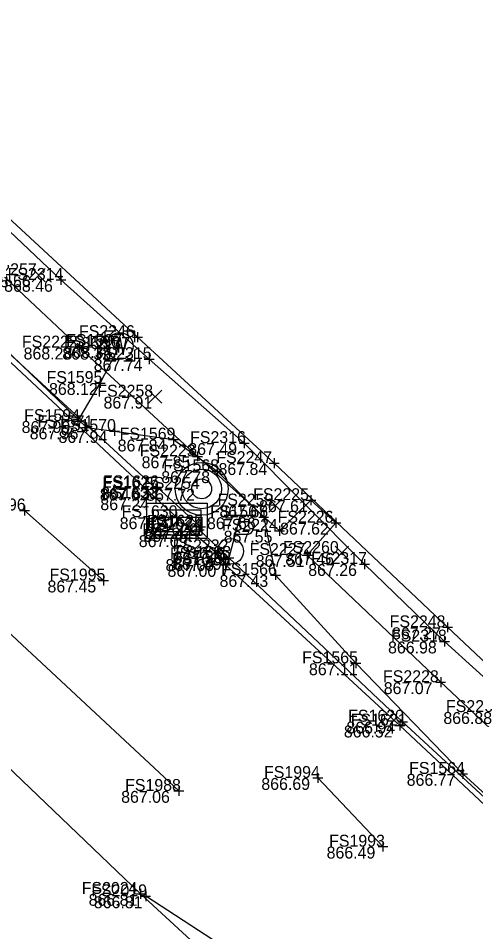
# Model space of a CAD drawing. Extents: x 1479420 to 1479833, y 379731 to 380103.
# Drawn here: x 1479719.9 to 1479766, y 379820.1 to 379912.2 of the extents above; entities that cross this region are included whole.
import ezdxf

# ---------------------------------------------------------------- set-up
doc = ezdxf.new("R2010")
doc.units = 0
for name, color, linetype in [('DR_X_Cells', 7, 'Continuous'), ('GK_Drainage_Nodes', 7, 'Continuous'), ('PM_X_Channelizing_Line', 7, 'Continuous'), ('PM_X_CL_Double_Solid', 7, 'Continuous'), ('PM_X_Lane_Line', 7, 'Continuous'), ('PV_X_Curb', 7, 'Continuous'), ('PV_X_Walk', 7, 'Continuous'), ('SV_X_Random_Point', 7, 'Continuous'), ('SV_X_Shot_Marker', 7, 'Continuous'), ('SV_X_Text_Elevation', 7, 'Continuous'), ('SV_X_Text_Name', 7, 'Continuous'), ('UT_X_Gas', 7, 'Continuous'), ('UT_X_Misc_Cells', 7, 'Continuous'), ('UT_X_Water', 7, 'Continuous'), ('UT_X_Water_Cells', 7, 'Continuous')]:
    doc.layers.add(name, color=color, linetype=linetype)

msp = doc.modelspace()

# ---------------------------------------------------------------- linework, layer by layer
at = {"layer": 'DR_X_Cells'}
for p, q in [((1479733.43, 379860.105), (1479735.184, 379861.863)), ((1479733.43, 379861.237), (1479734.054, 379861.863)), ((1479734.486, 379860.03), (1479736.314, 379861.863)), ((1479735.615, 379860.03), (1479737.444, 379861.863)), ((1479736.745, 379860.03), (1479738.43, 379861.719)), ((1479737.875, 379860.03), (1479738.43, 379860.587))]:
    msp.add_line(p, q, dxfattribs=at)
for points in [[(1479732.888, 379863.281), (1479738.972, 379863.281), (1479738.972, 379859.697), (1479732.888, 379859.697)], [(1479733.555, 379862.613), (1479738.305, 379862.613), (1479738.305, 379860.363), (1479733.555, 379860.363)], [(1479733.43, 379861.863), (1479738.43, 379861.863), (1479738.43, 379860.03), (1479733.43, 379860.03)]]:
    msp.add_lwpolyline(points, close=True, dxfattribs=at)
for radius in [2.667, 2, 1]:
    msp.add_circle((1479738.405, 379864.71), radius, dxfattribs=at)
at = {"layer": 'GK_Drainage_Nodes'}
for p, q in [((1479738.405, 379866.71), (1479738.405, 379866.71)), ((1479738.405, 379864.71), (1479738.405, 379864.71)), ((1479738.405, 379864.71), (1479738.405, 379864.71)), ((1479738.405, 379864.71), (1479738.405, 379864.71)), ((1479735.93, 379863.28), (1479735.93, 379863.28)), ((1479735.93, 379862.613), (1479735.93, 379862.613)), ((1479738.405, 379862.71), (1479738.405, 379862.71)), ((1479735.93, 379861.863), (1479735.93, 379861.863)), ((1479735.93, 379861.863), (1479735.93, 379861.863)), ((1479733.555, 379861.488), (1479733.555, 379861.488)), ((1479735.93, 379861.488), (1479735.93, 379861.488)), ((1479738.305, 379861.488), (1479738.305, 379861.488)), ((1479735.93, 379860.363), (1479735.93, 379860.363)), ((1479735.93, 379859.697), (1479735.93, 379859.697))]:
    msp.add_line(p, q, dxfattribs=at)
msp.add_circle((1479738.405, 379864.71), 2, dxfattribs=at)
at = {"layer": 'PM_X_Channelizing_Line'}
msp.add_lwpolyline([(1479685.324, 379881.456), (1479709.405, 379859.144), (1479736.1, 379834.256)], dxfattribs=at)
at = {"layer": 'PM_X_CL_Double_Solid'}
for points in [[(1479794.219, 379768.772), (1479779.093, 379781.771), (1479763.159, 379795.427), (1479746.619, 379810.624), (1479732.239, 379823.873), (1479714.719, 379840.653), (1479700.713, 379853.615), (1479677.934, 379875.066)], [(1479803.529, 379770.896), (1479781.948, 379790.708), (1479777.891, 379794.074), (1479768.812, 379800.571), (1479752.353, 379810.888), (1479732.762, 379823.628)]]:
    msp.add_lwpolyline(points, dxfattribs=at)
at = {"layer": 'PM_X_Lane_Line'}
for p, q in [((1479728.499, 379855.469), (1479720.54, 379862.536)), ((1479756.669, 379828.635), (1479750.1, 379835.56))]:
    msp.add_line(p, q, dxfattribs=at)
at = {"layer": 'PV_X_Curb'}
for points in [[(1479714.573, 379931.716), (1479714.771, 379922.599), (1479714.229, 379900.013), (1479714.491, 379898.192), (1479715.218, 379896.002), (1479717.036, 379893.796), (1479731.944, 379880.013), (1479745.709, 379867.308), (1479763.187, 379850.751), (1479775.061, 379839.578), (1479781.928, 379833.121), (1479783.777, 379830.713), (1479784.214, 379828.705), (1479783.141, 379825.906)], [(1479818.811, 379784.125), (1479817.439, 379785.583), (1479804.233, 379798.167), (1479791.741, 379810.033), (1479778.638, 379821.983), (1479775.464, 379824.819), (1479758.378, 379840.845), (1479740.8, 379857.042), (1479740.592, 379857.626), (1479737.808, 379860.038), (1479735.87, 379861.852), (1479733.787, 379863.763), (1479718.701, 379877.898), (1479705.478, 379890.334), (1479700.95, 379894.575), (1479699.048, 379897.264), (1479697.778, 379899.5), (1479696.445, 379902.732), (1479695.776, 379905.397), (1479695.475, 379907.419), (1479695.142, 379911.53), (1479695.083, 379915.321)], [(1479783.191, 379825.805), (1479782.298, 379824.723), (1479781.461, 379824.102), (1479780.469, 379823.552), (1479779.204, 379823.559), (1479778.041, 379823.771), (1479776.54, 379824.685), (1479775.613, 379825.569), (1479758.651, 379841.237), (1479741.143, 379857.755), (1479738.162, 379860.576), (1479738.292, 379860.892), (1479733.926, 379864.875), (1479733.77, 379864.743), (1479718.903, 379878.446), (1479705.833, 379890.72), (1479701.383, 379894.844), (1479699.526, 379897.551), (1479698.177, 379899.762), (1479696.913, 379902.812), (1479696.188, 379905.546), (1479696.149, 379907.481), (1479695.686, 379911.644), (1479695.62, 379915.117)]]:
    msp.add_lwpolyline(points, dxfattribs=at)
at = {"layer": 'PV_X_Walk'}
msp.add_lwpolyline([(1479714.407, 379931.65), (1479709.589, 379929.394), (1479706.362, 379927.006), (1479703.827, 379924.359), (1479702.38, 379922.179), (1479701.604, 379920.676), (1479701.232, 379918.285), (1479701.216, 379916.698), (1479701.871, 379912.679), (1479703.861, 379906.887), (1479705.425, 379903.147), (1479707.313, 379899.269), (1479709.707, 379895.256), (1479713.76, 379890.533), (1479726.083, 379878.959), (1479737.973, 379867.989), (1479746.242, 379860.487), (1479749.391, 379863.573), (1479751.936, 379861.299), (1479749.037, 379858.043), (1479762.483, 379845.218), (1479775.26, 379833.23), (1479781.252, 379827.717), (1479783.036, 379825.875)], dxfattribs=at)
at = {"layer": 'SV_X_Random_Point'}
for p, q in [((1479721.315, 379885.587), (1479722.649, 379886.922)), ((1479721.315, 379886.922), (1479722.649, 379885.587)), ((1479733.054, 379873.34), (1479734.388, 379874.675)), ((1479733.054, 379874.675), (1479734.388, 379873.34)), ((1479745.164, 379862.362), (1479746.498, 379863.697)), ((1479745.164, 379863.697), (1479746.498, 379862.362)), ((1479751.868, 379857.584), (1479753.202, 379858.919)), ((1479751.868, 379858.919), (1479753.202, 379857.584))]:
    msp.add_line(p, q, dxfattribs=at)
at = {"layer": 'SV_X_Shot_Marker'}
for p, q in [((1479723.725, 379885.781), (1479724.725, 379885.781)), ((1479724.225, 379886.281), (1479724.225, 379885.281)), ((1479724.225, 379885.781), (1479724.225, 379885.781)), ((1479731.444, 379880.013), (1479732.444, 379880.013)), ((1479731.944, 379880.513), (1479731.944, 379879.513)), ((1479731.944, 379880.013), (1479731.944, 379880.013)), ((1479726.083, 379879.459), (1479726.083, 379878.459)), ((1479730.011, 379879.447), (1479730.011, 379878.447)), ((1479725.583, 379878.959), (1479726.583, 379878.959)), ((1479726.083, 379878.959), (1479726.083, 379878.959)), ((1479729.511, 379878.947), (1479730.511, 379878.947)), ((1479730.011, 379878.947), (1479730.011, 379878.947)), ((1479733.117, 379878.295), (1479733.117, 379877.295)), ((1479732.617, 379877.795), (1479733.617, 379877.795)), ((1479733.117, 379877.795), (1479733.117, 379877.795)), ((1479728.18, 379875.882), (1479728.18, 379874.882)), ((1479727.68, 379875.382), (1479728.68, 379875.382)), ((1479728.18, 379875.382), (1479728.18, 379875.382)), ((1479725.91, 379872.046), (1479725.91, 379871.046)), ((1479725.41, 379871.546), (1479726.41, 379871.546)), ((1479725.91, 379871.546), (1479725.91, 379871.546)), ((1479726.29, 379870.913), (1479727.29, 379870.913)), ((1479726.79, 379871.413), (1479726.79, 379870.413)), ((1479726.79, 379870.913), (1479726.79, 379870.913)), ((1479729.608, 379871.044), (1479729.608, 379870.044)), ((1479729.108, 379870.544), (1479730.108, 379870.544)), ((1479729.608, 379870.544), (1479729.608, 379870.544)), ((1479735.551, 379870.184), (1479735.551, 379869.184)), ((1479735.051, 379869.684), (1479736.051, 379869.684)), ((1479735.551, 379869.684), (1479735.551, 379869.684)), ((1479742.197, 379869.326), (1479743.197, 379869.326)), ((1479742.697, 379869.826), (1479742.697, 379868.826)), ((1479742.697, 379869.326), (1479742.697, 379869.326)), ((1479737.973, 379868.489), (1479737.973, 379867.489)), ((1479737.473, 379867.989), (1479738.473, 379867.989)), ((1479737.973, 379867.989), (1479737.973, 379867.989)), ((1479745.209, 379867.308), (1479746.209, 379867.308)), ((1479745.709, 379867.808), (1479745.709, 379866.808)), ((1479745.709, 379867.308), (1479745.709, 379867.308)), ((1479739.447, 379866.49), (1479740.447, 379866.49)), ((1479739.947, 379866.99), (1479739.947, 379865.99)), ((1479739.947, 379866.49), (1479739.947, 379866.49)), ((1479733.926, 379865.375), (1479733.926, 379864.375)), ((1479733.27, 379864.743), (1479734.27, 379864.743)), ((1479733.426, 379864.875), (1479734.426, 379864.875)), ((1479733.77, 379865.243), (1479733.77, 379864.243)), ((1479733.77, 379864.743), (1479733.77, 379864.743)), ((1479733.926, 379864.875), (1479733.926, 379864.875)), ((1479733.287, 379863.763), (1479734.287, 379863.763)), ((1479733.787, 379864.263), (1479733.787, 379863.263)), ((1479733.787, 379863.763), (1479733.787, 379863.763)), ((1479748.891, 379863.573), (1479749.891, 379863.573)), ((1479749.391, 379864.073), (1479749.391, 379863.073)), ((1479749.391, 379863.573), (1479749.391, 379863.573)), ((1479720.04, 379862.536), (1479721.04, 379862.536)), ((1479720.54, 379863.036), (1479720.54, 379862.036)), ((1479720.54, 379862.536), (1479720.54, 379862.536)), ((1479735.37, 379861.852), (1479736.37, 379861.852)), ((1479735.87, 379862.352), (1479735.87, 379861.352)), ((1479735.87, 379861.852), (1479735.87, 379861.852)), ((1479744.15, 379861.847), (1479745.15, 379861.847)), ((1479744.65, 379862.347), (1479744.65, 379861.347)), ((1479744.65, 379861.847), (1479744.65, 379861.847)), ((1479751.936, 379861.799), (1479751.936, 379860.799)), ((1479737.792, 379860.892), (1479738.792, 379860.892)), ((1479738.162, 379861.076), (1479738.162, 379860.076)), ((1479738.292, 379861.392), (1479738.292, 379860.392)), ((1479738.292, 379860.892), (1479738.292, 379860.892)), ((1479746.242, 379860.987), (1479746.242, 379859.987)), ((1479751.436, 379861.299), (1479752.436, 379861.299)), ((1479751.936, 379861.299), (1479751.936, 379861.299)), ((1479737.308, 379860.038), (1479738.308, 379860.038)), ((1479737.662, 379860.576), (1479738.662, 379860.576)), ((1479737.808, 379860.538), (1479737.808, 379859.538)), ((1479737.808, 379860.038), (1479737.808, 379860.038)), ((1479738.162, 379860.576), (1479738.162, 379860.576)), ((1479745.742, 379860.487), (1479746.742, 379860.487)), ((1479746.242, 379860.487), (1479746.242, 379860.487)), ((1479740.592, 379858.126), (1479740.592, 379857.126)), ((1479741.143, 379858.255), (1479741.143, 379857.255)), ((1479748.537, 379858.043), (1479749.537, 379858.043)), ((1479749.037, 379858.543), (1479749.037, 379857.543)), ((1479749.037, 379858.043), (1479749.037, 379858.043)), ((1479740.092, 379857.626), (1479741.092, 379857.626)), ((1479740.3, 379857.042), (1479741.3, 379857.042)), ((1479740.592, 379857.626), (1479740.592, 379857.626)), ((1479740.643, 379857.755), (1479741.643, 379857.755)), ((1479740.8, 379857.542), (1479740.8, 379856.542)), ((1479740.8, 379857.042), (1479740.8, 379857.042)), ((1479741.143, 379857.755), (1479741.143, 379857.755)), ((1479754.316, 379857.131), (1479755.316, 379857.131)), ((1479754.816, 379857.631), (1479754.816, 379856.631)), ((1479754.816, 379857.131), (1479754.816, 379857.131)), ((1479745.833, 379856.523), (1479745.833, 379855.523)), ((1479727.999, 379855.469), (1479728.999, 379855.469)), ((1479728.499, 379855.969), (1479728.499, 379854.969)), ((1479728.499, 379855.469), (1479728.499, 379855.469)), ((1479745.333, 379856.023), (1479746.333, 379856.023)), ((1479745.833, 379856.023), (1479745.833, 379856.023)), ((1479762.687, 379850.751), (1479763.687, 379850.751)), ((1479763.187, 379851.251), (1479763.187, 379850.251)), ((1479763.187, 379850.751), (1479763.187, 379850.751)), ((1479762.869, 379849.818), (1479762.869, 379848.818)), ((1479762.369, 379849.318), (1479763.369, 379849.318)), ((1479762.869, 379849.318), (1479762.869, 379849.318)), ((1479753.429, 379847.124), (1479754.429, 379847.124)), ((1479753.929, 379847.624), (1479753.929, 379846.624)), ((1479753.929, 379847.124), (1479753.929, 379847.124)), ((1479761.983, 379845.218), (1479762.983, 379845.218)), ((1479762.483, 379845.718), (1479762.483, 379844.718)), ((1479762.483, 379845.218), (1479762.483, 379845.218)), ((1479758.378, 379841.345), (1479758.378, 379840.345)), ((1479758.651, 379841.737), (1479758.651, 379840.737)), ((1479757.878, 379840.845), (1479758.878, 379840.845)), ((1479758.151, 379841.237), (1479759.151, 379841.237)), ((1479758.378, 379840.845), (1479758.378, 379840.845)), ((1479758.651, 379841.237), (1479758.651, 379841.237)), ((1479750.1, 379836.06), (1479750.1, 379835.06)), ((1479764.201, 379835.97), (1479765.201, 379835.97)), ((1479764.701, 379836.47), (1479764.701, 379835.47)), ((1479764.701, 379835.97), (1479764.701, 379835.97)), ((1479749.6, 379835.56), (1479750.6, 379835.56)), ((1479750.1, 379835.56), (1479750.1, 379835.56)), ((1479735.6, 379834.256), (1479736.6, 379834.256)), ((1479736.1, 379834.756), (1479736.1, 379833.756)), ((1479736.1, 379834.256), (1479736.1, 379834.256)), ((1479756.169, 379828.635), (1479757.169, 379828.635)), ((1479756.669, 379829.135), (1479756.669, 379828.135)), ((1479756.669, 379828.635), (1479756.669, 379828.635)), ((1479731.739, 379823.873), (1479732.739, 379823.873)), ((1479732.239, 379824.373), (1479732.239, 379823.373)), ((1479732.239, 379823.873), (1479732.239, 379823.873)), ((1479732.762, 379824.128), (1479732.762, 379823.128)), ((1479732.262, 379823.628), (1479733.262, 379823.628)), ((1479732.762, 379823.628), (1479732.762, 379823.628))]:
    msp.add_line(p, q, dxfattribs=at)
at = {"layer": 'UT_X_Gas'}
msp.add_lwpolyline([(1479667.444, 379946.572), (1479666.862, 379942.802), (1479667.538, 379940.507), (1479675.403, 379934.504), (1479682.743, 379926.326), (1479692.421, 379916.824), (1479702.659, 379906.694), (1479713.881, 379895.567), (1479724.225, 379885.781), (1479733.117, 379877.795), (1479742.697, 379869.326), (1479754.816, 379857.131), (1479762.869, 379849.318), (1479772.436, 379840.641), (1479780.346, 379832.715), (1479784.901, 379828.191), (1479795.906, 379818.324), (1479806.128, 379806.719), (1479816.671, 379794.927)], dxfattribs=at)
at = {"layer": 'UT_X_Misc_Cells'}
for p, q in [((1479742.274, 379862.016), (1479740.668, 379856.016)), ((1479743.874, 379862.016), (1479740.674, 379862.016)), ((1479742.114, 379861.416), (1479742.964, 379861.416)), ((1479741.773, 379860.141), (1479742.964, 379860.141))]:
    msp.add_line(p, q, dxfattribs=at)
msp.add_circle((1479741.311, 379858.416), 1.3, dxfattribs=at)
msp.add_arc((1479742.977, 379860.778), 0.638, 268.8767, 91.1233, dxfattribs=at)
at = {"layer": 'UT_X_Water'}
for points in [[(1479682.752, 379913.809), (1479688.353, 379908.314), (1479695.924, 379900.161), (1479705.441, 379891.596), (1479719.261, 379878.171), (1479726.79, 379870.913), (1479729.608, 379870.544), (1479735.551, 379869.684), (1479739.947, 379866.49), (1479744.65, 379861.847), (1479745.833, 379856.023), (1479753.929, 379847.124), (1479764.701, 379835.97), (1479779.815, 379822.167), (1479798.248, 379804.283), (1479815.468, 379787.444)], [(1479725.91, 379871.546), (1479728.18, 379875.382), (1479730.011, 379878.947)]]:
    msp.add_lwpolyline(points, dxfattribs=at)
at = {"layer": 'UT_X_Water_Cells'}
msp.add_line((1479730.153, 379879.115), (1479730.153, 379879.115), dxfattribs=at)
for points in [[(1479729.753, 379880.615), (1479728.653, 379880.615), (1479728.653, 379879.515)], [(1479729.486, 379880.015), (1479729.82, 379878.215), (1479730.153, 379880.015), (1479730.486, 379878.215), (1479730.82, 379880.015)], [(1479731.653, 379879.515), (1479731.653, 379880.615), (1479730.553, 379880.615)], [(1479728.653, 379878.715), (1479728.653, 379877.615), (1479729.753, 379877.615)], [(1479730.553, 379877.615), (1479731.653, 379877.615), (1479731.653, 379878.715)]]:
    msp.add_lwpolyline(points, dxfattribs=at)
msp.add_circle((1479730.153, 379879.115), 1.35, dxfattribs=at)

# ---------------------------------------------------------------- texts
at = {"layer": 'SV_X_Text_Elevation'}
for s, height, p in [('868.56', 1.2, (1479716.266, 379885.055)), ('868.46', 1.2, (1479718.5, 379884.581)), ('868.37', 1.2, (1479726.285, 379878.813)), ('868.34', 1.2, (1479724.503, 379877.915)), ('868.23', 1.2, (1479720.461, 379877.759)), ('868.32', 1.2, (1479724.361, 379877.747)), ('867.74', 1.2, (1479727.524, 379876.595)), ('868.12', 1.2, (1479723.022, 379874.182)), ('867.91', 1.2, (1479728.514, 379872.807)), ('867.99', 1.2, (1479720.26, 379870.346)), ('867.96', 1.2, (1479721.074, 379869.713)), ('867.94', 1.2, (1479723.977, 379869.344)), ('867.84', 1.2, (1479729.939, 379868.484)), ('867.49', 1.2, (1479737.056, 379868.126)), ('867.85', 1.2, (1479732.351, 379866.789)), ('867.84', 1.2, (1479740.097, 379866.108)), ('867.78', 1.2, (1479734.335, 379865.29)), ('867.62', 1.2, (1479728.139, 379863.543)), ('867.63', 1.2, (1479728.285, 379863.675)), ('867.72', 1.2, (1479732.812, 379863.51)), ('867.24', 1.2, (1479728.194, 379862.563)), ('867.61', 1.2, (1479744.184, 379862.373)), ('867.65', 1.2, (1479740.19, 379861.83)), ('867.04', 1.2, (1479730.144, 379860.652)), ('867.02', 0.2, (1479734.976, 379861.663)), ('867.66', 1.2, (1479738.934, 379860.647)), ('867.42', 1.2, (1479732.67, 379859.692)), ('867.62', 1.2, (1479746.305, 379860.099)), ('867.09', 1.2, (1479732.063, 379858.838)), ('867.44', 1.2, (1479732.54, 379859.376)), ('867.55', 1.2, (1479740.62, 379859.287)), ('867.50', 1.2, (1479735.585, 379857.216)), ('867.51', 1.2, (1479743.849, 379856.843)), ('867.46', 1.2, (1479746.828, 379857.051)), ('867.00', 1.2, (1479734.753, 379856.426)), ('867.00', 1.2, (1479734.961, 379855.842)), ('867.49', 1.2, (1479735.502, 379856.555)), ('867.26', 1.2, (1479749.138, 379855.931)), ('867.45', 1.2, (1479722.868, 379854.269)), ('867.43', 1.2, (1479740.202, 379854.823)), ('867.27', 1.2, (1479757.584, 379849.551)), ('866.98', 1.2, (1479757.181, 379848.118)), ('867.11', 1.2, (1479749.214, 379845.924)), ('867.07', 1.2, (1479756.748, 379844.018)), ('866.88', 1.2, (1479762.754, 379841.007)), ('866.52', 1.2, (1479752.728, 379839.645)), ('866.94', 1.2, (1479752.982, 379840.037)), ('866.77', 1.2, (1479759.06, 379834.77)), ('866.69', 1.2, (1479744.412, 379834.36)), ('867.06', 1.2, (1479730.289, 379833.056)), ('866.49', 1.2, (1479750.991, 379827.435)), ('866.81', 1.2, (1479727.013, 379822.673)), ('866.81', 1.2, (1479727.536, 379822.428))]:
    msp.add_text(s, height=height, dxfattribs=at).set_placement(p)
at = {"layer": 'SV_X_Text_Name'}
for s, height, p in [('FS2257', 1.2, (1479716.162, 379886.255)), ('FS2314', 1.2, (1479718.85, 379885.781)), ('FS2246', 1.2, (1479726.039, 379880.013)), ('FS2222', 1.2, (1479720.291, 379878.959)), ('FS1596', 1.2, (1479724.532, 379878.947)), ('FS1597', 1.2, (1479724.749, 379879.115)), ('FS2315', 1.2, (1479727.732, 379877.795)), ('FS1595', 1.2, (1479722.776, 379875.382)), ('FS2258', 1.2, (1479727.892, 379874.007)), ('FS1594', 1.2, (1479720.516, 379871.546)), ('FS1571', 1.2, (1479721.858, 379870.913)), ('FS1570', 1.2, (1479724.138, 379870.544)), ('FS1569', 1.2, (1479730.138, 379869.684)), ('FS2316', 1.2, (1479737.237, 379869.326)), ('FS2223', 1.2, (1479732.172, 379867.989)), ('FS2247', 1.2, (1479739.88, 379867.308)), ('FS1568', 1.2, (1479734.534, 379866.49)), ('FS1627', 1.2, (1479728.385, 379864.743)), ('FS1626', 1.2, (1479728.466, 379864.875)), ('FS2254', 1.2, (1479732.594, 379864.71)), ('FS1633', 1.2, (1479728.364, 379863.763)), ('FS2225', 1.2, (1479743.59, 379863.573)), ('FS1996', 1.2, (1479715.042, 379862.536)), ('FS2259', 1.2, (1479740.002, 379863.03)), ('FS1630', 1.2, (1479730.343, 379861.852)), ('FS1567', 1.2, (1479739.246, 379861.847)), ('FS2226', 1.2, (1479746.059, 379861.299)), ('FS1624', 1.2, (1479732.787, 379860.576)), ('FS1625', 1.2, (1479732.907, 379860.892)), ('FS1632', 0.2, (1479735.028, 379861.863)), ('FS2224', 1.2, (1479740.45, 379860.487)), ('FS1629', 1.2, (1479732.414, 379860.038)), ('FS1628', 1.2, (1479735.198, 379857.626)), ('FS2232', 1.2, (1479735.482, 379858.416)), ('FS1623', 1.2, (1479735.758, 379857.755)), ('FS2227', 1.2, (1479743.236, 379858.043)), ('FS2260', 1.2, (1479746.592, 379858.251)), ('FS1622', 1.2, (1479735.425, 379857.042)), ('FS2317', 1.2, (1479749.431, 379857.131)), ('FS1566', 1.2, (1479740.354, 379856.023)), ('FS1995', 1.2, (1479723.076, 379855.469)), ('FS2248', 1.2, (1479757.348, 379850.751)), ('FS2318', 1.2, (1479757.475, 379849.318)), ('FS1565', 1.2, (1479748.525, 379847.124)), ('FS2228', 1.2, (1479756.672, 379845.218)), ('FS2261', 1.2, (1479763.018, 379842.207)), ('FS1620', 1.2, (1479753.162, 379841.237)), ('FS1621', 1.2, (1479753.427, 379840.845)), ('FS1994', 1.2, (1479744.687, 379835.56)), ('FS1564', 1.2, (1479759.307, 379835.97)), ('FS1988', 1.2, (1479730.687, 379834.256)), ('FS1993', 1.2, (1479751.246, 379828.635)), ('FS2024', 1.2, (1479726.315, 379823.873)), ('FS2019', 1.2, (1479727.273, 379823.628))]:
    msp.add_text(s, height=height, dxfattribs=at).set_placement(p)

doc.saveas('drawing.dxf')
